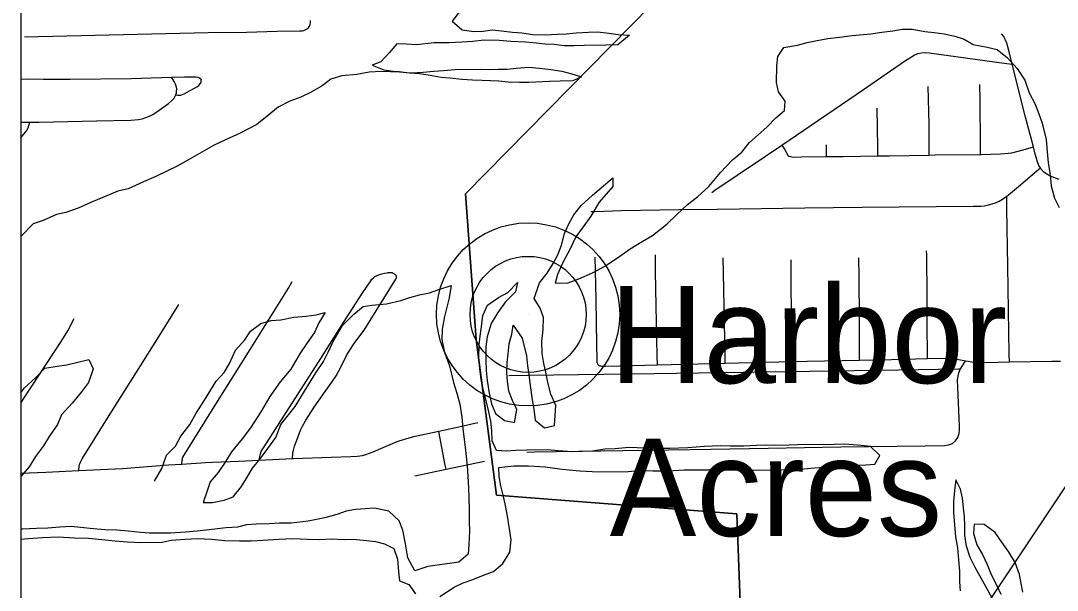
# Model space of a CAD drawing. Extents: x -12 to 34, y 0 to 22.
# Drawn here: x 2.1 to 2.942, y 18.646 to 19.109 of the extents above; entities that cross this region are included whole.
import ezdxf

# ---------------------------------------------------------------- set-up
doc = ezdxf.new("R2010")
doc.units = 0
for name, color, linetype in [('GM_X_Adjacent_County', 7, 'Continuous'), ('GM_X_Airport_Location_Class_2', 7, 'Continuous'), ('GM_X_Interstate_Location', 7, 'Continuous'), ('GM_X_Major_River', 7, 'Continuous'), ('GM_X_Minor_Lake', 7, 'Continuous'), ('GM_X_Section_Text', 7, 'Continuous'), ('GM_X_Township_Subdivision', 7, 'Continuous')]:
    doc.layers.add(name, color=color, linetype=linetype)

msp = doc.modelspace()

# ---------------------------------------------------------------- linework, layer by layer
at = {"layer": 'GM_X_Adjacent_County'}
msp.add_lwpolyline([(4.30775, 20.76949), (2.25839, 17.69538), (4.30775, 20.40004)], close=True, dxfattribs=at)
at = {"layer": 'GM_X_Airport_Location_Class_2'}
for points in [[(2.1, 20.9), (2.1, 15.61304)], [(2.1, 20.9), (2.1, 17.96636)], [(2.68959, 18.49311), (2.68165, 18.70783), (2.48634, 18.72302), (2.46988, 18.8495), (2.4613, 18.96781), (2.96471, 19.47995), (3.12115, 19.56992), (3.19049, 19.59855), (3.18766, 19.70043), (3.36569, 19.80374), (3.38045, 19.82011), (3.38989, 19.8456), (3.42854, 20.1304), (3.40914, 20.1567), (3.40388, 20.16065), (3.39697, 20.15703), (3.38185, 20.15637), (3.37182, 20.18876), (3.3637, 20.21774), (3.34173, 20.25863), (3.3271, 20.27754), (3.2883, 20.32785), (3.27433, 20.35119), (3.21662, 20.37881)], [(3.50022, 20.0768), (3.42854, 20.1304), (3.38989, 19.8456), (3.38045, 19.82011), (3.36569, 19.80374), (3.18766, 19.70043), (3.19049, 19.59855), (3.12115, 19.56992), (2.96471, 19.47995), (2.4613, 18.96781), (2.46988, 18.8495), (2.48634, 18.72302), (2.68165, 18.70783), (2.68959, 18.49311)]]:
    msp.add_lwpolyline(points, dxfattribs=at)
at = {"layer": 'GM_X_Interstate_Location'}
for radius in [0.0744, 0.04716]:
    msp.add_circle((2.51205, 18.86996), radius, dxfattribs=at)
at = {"layer": 'GM_X_Major_River'}
for p, q in [((2.1, 19.0262), (2.10749, 19.02616)), ((2.67207, 18.83038), (2.72649, 18.83162)), ((2.29354, 18.75149), (2.32067, 18.75297)), ((2.44541, 18.74421), (2.47657, 18.75081)), ((2.42013, 18.73885), (2.44541, 18.74421))]:
    msp.add_line(p, q, dxfattribs=at)
for points in [[(2.10297, 19.09531), (2.2523, 19.09884), (2.28331, 19.09936), (2.30812, 19.10009), (2.32677, 19.10024), (2.32848, 19.10033), (2.32988, 19.10062), (2.33104, 19.10102), (2.33258, 19.10181), (2.33308, 19.10219), (2.3337, 19.10278), (2.33448, 19.10405), (2.33502, 19.10541), (2.33536, 19.10696), (2.33542, 19.1087)], [(2.90517, 19.07327), (2.90234, 19.08445), (2.90069, 19.09037), (2.89846, 19.0958), (2.89659, 19.09779)], [(2.71812, 19.00753), (2.78454, 19.05264), (2.81777, 19.07554), (2.82566, 19.08049), (2.82848, 19.08177), (2.83147, 19.08246), (2.83456, 19.08259), (2.83766, 19.08235), (2.89879, 19.07413), (2.90517, 19.07327)], [(2.92239, 19.00597), (2.91606, 19.03019), (2.90517, 19.07327)], [(2.1, 19.06106), (2.10601, 19.06127), (2.11839, 19.06093), (2.14006, 19.06114), (2.1896, 19.06164), (2.22244, 19.06263)], [(2.22244, 19.06263), (2.23294, 19.06293), (2.24221, 19.06283), (2.2437, 19.06266), (2.24475, 19.06228), (2.24554, 19.06188), (2.24617, 19.06128), (2.24652, 19.06039)], [(2.22598, 19.04829), (2.22644, 19.04987), (2.2266, 19.05135), (2.22664, 19.05308), (2.22637, 19.05448), (2.22566, 19.05688), (2.22459, 19.05922), (2.22244, 19.06263)], [(2.22598, 19.04829), (2.22771, 19.04792), (2.23014, 19.04811), (2.23271, 19.04903), (2.24303, 19.0547), (2.24451, 19.05591), (2.24544, 19.05698), (2.24603, 19.05773), (2.24642, 19.05863), (2.24654, 19.05952), (2.24652, 19.06039)], [(2.83769, 18.99937), (2.83769, 19.00576), (2.8377, 19.02425), (2.83703, 19.05507)], [(2.87938, 18.99985), (2.87934, 19.00689), (2.87917, 19.04422), (2.87879, 19.05666)], [(2.10749, 19.02616), (2.11497, 19.02611), (2.16158, 19.02717), (2.18952, 19.02771), (2.19569, 19.02834), (2.19875, 19.02894), (2.20172, 19.02982), (2.20457, 19.031), (2.2073, 19.03244), (2.21248, 19.03589), (2.22005, 19.04137), (2.22254, 19.04336), (2.22454, 19.04564), (2.22598, 19.04829)], [(2.796, 18.99868), (2.79596, 19.00532), (2.79584, 19.02147), (2.79555, 19.03761)], [(2.1, 19.01336), (2.10473, 19.01919), (2.10601, 19.02159), (2.10749, 19.02616)], [(2.66119, 18.96908), (2.66379, 18.97077), (2.68179, 18.98295), (2.70494, 18.99858), (2.71812, 19.00753)], [(2.71812, 19.00753), (2.72014, 19.0042), (2.72337, 18.99887), (2.7239, 18.99852), (2.72755, 18.99779), (2.73371, 18.99801), (2.7544, 18.99818)], [(2.7544, 18.99818), (2.75439, 19.0008), (2.75436, 19.00758)], [(2.796, 18.99868), (2.80536, 18.99882), (2.83769, 18.99937)], [(2.83769, 18.99937), (2.84267, 18.99946), (2.87938, 18.99985)], [(2.87938, 18.99985), (2.88, 18.99986), (2.8956, 19.00028), (2.90184, 19.00081), (2.90495, 19.00133), (2.91403, 19.00374), (2.92239, 19.00597)], [(2.92808, 18.98902), (2.92685, 18.99103), (2.9256, 18.99399), (2.92392, 19.00012), (2.92239, 19.00597)], [(2.7544, 18.99818), (2.76801, 18.99828), (2.796, 18.99868)], [(2.9007, 18.96608), (2.90226, 18.96721), (2.9118, 18.97516), (2.92362, 18.98523), (2.92808, 18.98902)], [(2.94326, 18.97953), (2.93907, 18.98109), (2.93614, 18.98234), (2.93332, 18.98388), (2.93073, 18.98581), (2.92855, 18.98825), (2.92808, 18.98902)], [(2.56304, 18.95352), (2.56614, 18.95368), (2.58787, 18.95443), (2.63444, 18.95508), (2.66548, 18.95554), (2.7369, 18.95651), (2.78347, 18.95698), (2.87351, 18.95777), (2.87972, 18.95794), (2.8828, 18.95827), (2.88584, 18.95886), (2.88884, 18.95967), (2.89175, 18.96072), (2.89457, 18.96202), (2.89725, 18.96356), (2.9007, 18.96608)], [(2.90289, 18.83132), (2.90279, 18.83767), (2.90164, 18.90919), (2.90087, 18.95583), (2.9007, 18.96608)], [(2.56889, 18.82902), (2.56832, 18.83009), (2.56814, 18.83087), (2.56811, 18.8337), (2.56779, 18.84516), (2.56737, 18.88231), (2.56647, 18.91636)], [(2.61711, 18.82901), (2.61695, 18.8363), (2.61611, 18.87681), (2.61552, 18.90486), (2.61538, 18.91832)], [(2.67207, 18.83038), (2.67199, 18.83522), (2.67156, 18.86313), (2.67068, 18.90342), (2.6704, 18.91582)], [(2.78124, 18.83272), (2.78121, 18.83782), (2.78105, 18.86589), (2.78088, 18.9002), (2.78066, 18.9158)], [(2.83641, 18.83421), (2.83634, 18.83984), (2.83611, 18.85871), (2.8361, 18.8933), (2.83589, 18.90901), (2.83578, 18.91844), (2.83569, 18.92157)], [(2.72649, 18.83162), (2.7264, 18.8386), (2.72569, 18.89218), (2.72556, 18.91424)], [(2.29354, 18.75149), (2.29386, 18.75354), (2.29463, 18.75661), (2.29539, 18.75857), (2.34363, 18.83426), (2.36209, 18.86325), (2.37718, 18.88707), (2.38424, 18.89731), (2.38525, 18.89845), (2.38637, 18.89956), (2.38769, 18.90063), (2.38936, 18.90163), (2.39125, 18.90239), (2.39322, 18.90293), (2.39545, 18.90335), (2.39787, 18.90367)], [(2.32067, 18.75297), (2.32109, 18.7573), (2.32158, 18.75981), (2.32242, 18.76281), (2.32501, 18.77), (2.3272, 18.77584), (2.32848, 18.77866), (2.3315, 18.78408), (2.33824, 18.79456), (2.34725, 18.80727), (2.35275, 18.81483), (2.35611, 18.82005), (2.36061, 18.82821), (2.36466, 18.83663), (2.36616, 18.83935), (2.37139, 18.84706), (2.37884, 18.85704), (2.40454, 18.89855), (2.40507, 18.89959), (2.40524, 18.90021), (2.4052, 18.90091), (2.4049, 18.90152), (2.40395, 18.9023), (2.40312, 18.90289), (2.40255, 18.90321), (2.40165, 18.90364), (2.40054, 18.90384), (2.39787, 18.90367)], [(2.2309, 18.74839), (2.23109, 18.7517), (2.23126, 18.75269), (2.2317, 18.754), (2.2584, 18.79715), (2.28639, 18.84152), (2.30926, 18.87818), (2.31741, 18.89127), (2.32045, 18.89664)], [(2.14731, 18.74311), (2.14736, 18.74657), (2.14761, 18.748), (2.14846, 18.75002), (2.14976, 18.75272), (2.17051, 18.78561), (2.19727, 18.82827), (2.21368, 18.85435), (2.22828, 18.87795)], [(2.1, 18.79791), (2.10287, 18.80213), (2.13342, 18.84872), (2.13819, 18.85668), (2.14331, 18.8666)], [(2.72649, 18.83162), (2.73879, 18.8319), (2.78124, 18.83272)], [(2.78124, 18.83272), (2.80717, 18.83323), (2.83641, 18.83421)], [(2.83641, 18.83421), (2.84138, 18.83438), (2.85388, 18.83427), (2.85701, 18.83409), (2.86324, 18.83312), (2.86733, 18.83231)], [(2.86333, 18.82583), (2.86557, 18.82946), (2.86733, 18.83231)], [(2.86733, 18.83231), (2.8693, 18.83191), (2.87232, 18.8314), (2.88461, 18.83097), (2.90289, 18.83132)], [(2.90289, 18.83132), (2.93744, 18.83198), (2.94454, 18.83208)], [(2.4965, 18.8203), (2.512, 18.82059), (2.61437, 18.82197), (2.81289, 18.82504), (2.86156, 18.8258), (2.86333, 18.82583)], [(2.5111, 18.75817), (2.51731, 18.75839), (2.58884, 18.75953), (2.62615, 18.75994), (2.66039, 18.76051), (2.70703, 18.76133), (2.76614, 18.76233), (2.83456, 18.76329), (2.85019, 18.76358), (2.85342, 18.76402), (2.85657, 18.76513), (2.85927, 18.76718), (2.86113, 18.77), (2.86209, 18.77313), (2.86242, 18.77636), (2.86241, 18.77956), (2.86096, 18.81071), (2.86088, 18.81687), (2.86118, 18.81984), (2.86193, 18.82263), (2.86291, 18.82514), (2.86333, 18.82583)], [(2.56889, 18.82902), (2.56957, 18.82848), (2.57029, 18.82822), (2.57107, 18.82808), (2.57203, 18.82804), (2.57465, 18.82803), (2.58646, 18.82815), (2.61711, 18.82901)], [(2.61711, 18.82901), (2.6393, 18.82963), (2.67207, 18.83038)], [(2.4395, 18.77517), (2.45325, 18.7782), (2.4712, 18.78226)], [(2.39446, 18.76181), (2.40574, 18.76664), (2.41155, 18.76862), (2.42043, 18.77095), (2.4395, 18.77517)], [(2.44541, 18.74421), (2.44476, 18.7476), (2.44037, 18.77062), (2.4395, 18.77517)], [(2.32067, 18.75297), (2.32144, 18.75301), (2.35216, 18.75391), (2.36816, 18.75442), (2.37329, 18.7548), (2.37764, 18.75545), (2.3803, 18.75614), (2.38613, 18.75829), (2.39446, 18.76181)], [(2.14731, 18.74311), (2.18276, 18.74482), (2.2201, 18.74763), (2.2309, 18.74839)], [(2.2309, 18.74839), (2.25012, 18.74974), (2.25566, 18.74999)], [(2.25566, 18.74999), (2.277, 18.7507), (2.29354, 18.75149)], [(2.1, 18.74098), (2.12045, 18.74182), (2.14731, 18.74311)]]:
    msp.add_lwpolyline(points, dxfattribs=at)
at = {"layer": 'GM_X_Minor_Lake'}
for points in [[(2.45685, 19.11657), (2.45044, 19.10818), (2.45845, 19.10099), (2.46795, 19.09989), (2.47554, 19.09993), (2.48275, 19.1011), (2.49035, 19.10038), (2.49946, 19.09928), (2.50706, 19.09856), (2.5158, 19.09746), (2.52605, 19.09713), (2.53592, 19.09755), (2.54313, 19.09797), (2.5511, 19.09877), (2.56097, 19.09919), (2.56856, 19.09961), (2.57768, 19.09851), (2.58528, 19.09741), (2.59439, 19.09669), (2.58494, 19.08904), (2.57507, 19.08861), (2.55761, 19.08853), (2.54926, 19.08811), (2.54129, 19.08807), (2.53293, 19.08918), (2.52571, 19.08952), (2.51849, 19.09025), (2.51014, 19.09097), (2.49799, 19.09167), (2.48849, 19.09239), (2.47634, 19.09271), (2.46685, 19.09152), (2.45812, 19.0911), (2.44787, 19.09067), (2.43573, 19.09061), (2.42131, 19.08903), (2.41295, 19.08936), (2.40536, 19.08971), (2.39932, 19.08246), (2.39252, 19.0752), (2.38532, 19.0725), (2.39484, 19.06875), (2.40434, 19.06727), (2.41687, 19.06619), (2.42674, 19.06662), (2.43547, 19.06742), (2.44344, 19.06822), (2.45292, 19.06902), (2.47342, 19.06912), (2.48064, 19.06877), (2.48785, 19.06919), (2.49506, 19.06922), (2.50227, 19.07002), (2.51252, 19.07083), (2.52126, 19.07011), (2.53037, 19.06901), (2.53949, 19.06753), (2.54748, 19.06529)], [(2.49588, 18.83804), (2.4966, 18.84603), (2.49883, 18.85403), (2.49994, 18.86126), (2.5072, 18.85065), (2.5107, 18.83621), (2.51149, 18.82823), (2.51267, 18.82101), (2.51385, 18.81227), (2.51544, 18.80049), (2.51661, 18.7929), (2.5178, 18.78416), (2.52542, 18.77773), (2.53339, 18.77967), (2.53444, 18.79602), (2.5306, 18.80513), (2.52828, 18.81348), (2.52633, 18.82298), (2.52477, 18.8302), (2.52359, 18.83818), (2.52316, 18.84806), (2.52425, 18.85757), (2.52458, 18.86746), (2.52188, 18.87505), (2.51691, 18.88301), (2.5214, 18.89558), (2.52743, 18.90359), (2.53233, 18.91122), (2.53609, 18.91846), (2.53909, 18.92608), (2.54169, 18.9356), (2.54507, 18.9436), (2.54921, 18.95084), (2.55524, 18.95848), (2.56431, 18.96689), (2.57338, 18.97453), (2.58095, 18.98103), (2.58098, 18.97381), (2.56966, 18.96121), (2.56288, 18.94977), (2.55685, 18.94099), (2.55082, 18.93298), (2.54594, 18.92269), (2.5403, 18.91202), (2.53579, 18.90249), (2.53393, 18.89526), (2.54456, 18.89569), (2.55327, 18.89877), (2.56426, 18.90377), (2.57486, 18.90952), (2.58659, 18.91718), (2.59491, 18.9233), (2.60475, 18.92905), (2.61308, 18.93404), (2.6248, 18.94322), (2.63273, 18.95124), (2.64142, 18.95927), (2.64974, 18.96539), (2.65881, 18.9738), (2.66824, 18.98525), (2.67806, 18.99556), (2.68562, 19.00168), (2.69166, 19.00932), (2.69884, 19.01581), (2.70602, 19.02193), (2.7132, 19.02957), (2.72038, 19.03569), (2.72072, 19.0433), (2.71536, 19.05087), (2.71381, 19.05847), (2.71412, 19.07178), (2.71484, 19.07939), (2.71974, 19.08664), (2.73073, 19.08859), (2.7387, 19.09091), (2.74666, 19.09247), (2.75539, 19.09403), (2.76487, 19.09522), (2.77512, 19.09641), (2.79029, 19.098), (2.7994, 19.09918), (2.80813, 19.10037), (2.81571, 19.10154), (2.82407, 19.10158), (2.83433, 19.09973), (2.84192, 19.09901), (2.8499, 19.0979), (2.85864, 19.09604), (2.86625, 19.09342), (2.87348, 19.08927), (2.88489, 19.08704), (2.89287, 19.08518), (2.90126, 19.07837), (2.90927, 19.06967), (2.9154, 19.06019), (2.91887, 19.04994), (2.92347, 19.04122), (2.92693, 19.03287), (2.92963, 19.02527), (2.93273, 19.01198), (2.93354, 19.0021)], [(2.54748, 19.06529), (2.55546, 19.06304), (2.54827, 19.05959), (2.53802, 19.05954), (2.52929, 19.05912), (2.51259, 19.05828), (2.50499, 19.05824), (2.49588, 19.05858), (2.48828, 19.0593), (2.47461, 19.06), (2.46702, 19.06034), (2.45828, 19.06068), (2.44878, 19.06178), (2.44157, 19.0625), (2.43245, 19.06398), (2.42371, 19.06546), (2.41573, 19.0658), (2.40737, 19.0669), (2.40016, 19.06687), (2.39295, 19.06722), (2.38308, 19.06679), (2.37284, 19.06484), (2.36069, 19.06364), (2.35197, 19.06094), (2.34479, 19.05558), (2.33532, 19.05021), (2.32737, 19.04637), (2.31866, 19.04329), (2.30919, 19.0383), (2.30011, 19.03103), (2.2918, 19.02415), (2.27817, 19.01724), (2.26642, 19.01186), (2.25658, 19.00725), (2.24711, 19.00188), (2.23576, 18.99536), (2.22705, 18.99038), (2.2191, 18.98654), (2.20963, 18.98193), (2.19978, 18.9777), (2.18728, 18.97194), (2.17894, 18.97), (2.16681, 18.965), (2.15734, 18.96115), (2.14674, 18.95616), (2.13651, 18.95268), (2.12892, 18.95113), (2.11832, 18.94614), (2.10998, 18.94343), (2.1, 18.93334)], [(2.93354, 19.0021), (2.93435, 18.99298), (2.93592, 18.98348), (2.93672, 18.97436), (2.93943, 18.96448), (2.94327, 18.9569)], [(2.20863, 18.7344), (2.21465, 18.7447), (2.21839, 18.75574), (2.22557, 18.763), (2.23008, 18.771), (2.23724, 18.78054), (2.24251, 18.78969), (2.24929, 18.80037), (2.25871, 18.81562), (2.26512, 18.82288), (2.26964, 18.83012), (2.27452, 18.84079), (2.28207, 18.84919), (2.28659, 18.85644), (2.29491, 18.86256), (2.30325, 18.86488), (2.31122, 18.86568), (2.32184, 18.86763), (2.33171, 18.86844), (2.34005, 18.86962), (2.34726, 18.87156), (2.34199, 18.86317), (2.33861, 18.85517), (2.33258, 18.84677), (2.32693, 18.83838), (2.3194, 18.82542), (2.31072, 18.81511), (2.30243, 18.80329), (2.2949, 18.7907), (2.28662, 18.77773), (2.27983, 18.76896), (2.27115, 18.75827), (2.26663, 18.75065), (2.26023, 18.74149), (2.25381, 18.73386), (2.25082, 18.7251), (2.2482, 18.7171), (2.2558, 18.71714), (2.26528, 18.71908), (2.27248, 18.72178), (2.27927, 18.73018), (2.28378, 18.7378), (2.2883, 18.74505), (2.29434, 18.75268), (2.30075, 18.76107), (2.30716, 18.76985), (2.31128, 18.78051), (2.32297, 18.79502), (2.3305, 18.8076), (2.33954, 18.82247), (2.34595, 18.83163), (2.3497, 18.83925), (2.35383, 18.84801), (2.36136, 18.86098), (2.37042, 18.87015), (2.37798, 18.87626), (2.3852, 18.87744), (2.39696, 18.87864), (2.40871, 18.88135), (2.41591, 18.88367), (2.42388, 18.88599), (2.43184, 18.88755), (2.43942, 18.89025), (2.44965, 18.89334), (2.44781, 18.88344), (2.44409, 18.86822), (2.44224, 18.85794), (2.44191, 18.84957), (2.44424, 18.83894), (2.44809, 18.82831), (2.45158, 18.81464), (2.45428, 18.80591), (2.4566, 18.79717), (2.45818, 18.78654), (2.45899, 18.77703), (2.46096, 18.76221), (2.46256, 18.74701), (2.46338, 18.73409), (2.46382, 18.72231), (2.46427, 18.71014), (2.46431, 18.70178), (2.46435, 18.69379), (2.46402, 18.68315), (2.46331, 18.67516), (2.45575, 18.66866), (2.44816, 18.66748), (2.4383, 18.6663), (2.43071, 18.66512), (2.4201, 18.66165), (2.41435, 18.67227), (2.41239, 18.68366), (2.41043, 18.69468), (2.40736, 18.70227), (2.39896, 18.71021), (2.38718, 18.71244), (2.37997, 18.71202), (2.372, 18.71161), (2.36442, 18.71005), (2.35684, 18.70735), (2.34698, 18.70464), (2.33332, 18.70192)], [(2.48388, 18.66119), (2.49144, 18.66769), (2.49709, 18.67684), (2.49818, 18.68673), (2.49699, 18.69585), (2.49503, 18.70763), (2.49347, 18.71598), (2.49191, 18.7232), (2.48998, 18.73079), (2.48842, 18.73839), (2.48838, 18.74562), (2.50052, 18.74682), (2.51229, 18.74687), (2.52597, 18.74617), (2.53964, 18.74434), (2.55408, 18.74289), (2.56927, 18.7422), (2.59319, 18.74231), (2.60153, 18.74311), (2.6133, 18.74279), (2.62545, 18.74284), (2.63874, 18.74367), (2.66076, 18.74377), (2.67177, 18.74345), (2.71391, 18.74365), (2.7215, 18.74406), (2.73023, 18.7441), (2.74466, 18.74531), (2.7568, 18.74613), (2.76553, 18.74655), (2.77502, 18.74736), (2.78641, 18.74779), (2.79362, 18.74821), (2.79776, 18.75545), (2.79012, 18.76264), (2.77987, 18.76373), (2.76885, 18.76444), (2.7605, 18.7644), (2.75063, 18.76397), (2.73696, 18.76429), (2.72406, 18.76384), (2.71191, 18.76341), (2.7047, 18.76375), (2.69748, 18.76334), (2.68723, 18.76291), (2.67623, 18.76286), (2.66825, 18.7632), (2.65534, 18.76276), (2.64168, 18.76155), (2.62688, 18.7611), (2.61435, 18.76104), (2.59385, 18.76171), (2.58284, 18.76089), (2.57449, 18.76047), (2.56425, 18.7589), (2.55589, 18.75848), (2.54792, 18.75845), (2.53653, 18.75915), (2.52817, 18.75987), (2.51109, 18.75979), (2.50198, 18.75937), (2.49439, 18.75895), (2.48641, 18.75929), (2.48296, 18.76726), (2.48254, 18.77525), (2.48173, 18.78322), (2.48018, 18.79082), (2.47824, 18.7988), (2.47553, 18.80905), (2.47397, 18.81703), (2.47278, 18.82615), (2.47198, 18.83451), (2.4723, 18.84515), (2.47302, 18.85238), (2.47412, 18.85999), (2.47522, 18.86912), (2.47897, 18.87751), (2.48805, 18.88363), (2.49562, 18.88785), (2.50355, 18.89587), (2.5017, 18.88826), (2.49376, 18.88024), (2.48735, 18.87146), (2.48208, 18.86269), (2.47872, 18.85165), (2.47762, 18.84366), (2.47768, 18.83301), (2.4781, 18.82427), (2.47891, 18.81629), (2.48048, 18.80603), (2.48242, 18.7973), (2.4855, 18.78933), (2.49274, 18.78366), (2.5011, 18.78218), (2.50295, 18.79283), (2.49949, 18.80004), (2.49641, 18.80763), (2.49523, 18.81561), (2.49482, 18.82283), (2.49516, 18.83082), (2.49588, 18.83804)], [(2.1, 18.80635), (2.10269, 18.80994), (2.11214, 18.81873), (2.11969, 18.82637), (2.12956, 18.82794), (2.13752, 18.82911), (2.14625, 18.83106), (2.15534, 18.83338), (2.1588, 18.82579), (2.15506, 18.81475), (2.14941, 18.80712), (2.14186, 18.79796), (2.13318, 18.78841), (2.1298, 18.78041), (2.12302, 18.77088), (2.1185, 18.76325), (2.11209, 18.75447), (2.10682, 18.74608), (2.1, 18.73829)], [(2.88909, 18.63878), (2.88411, 18.64826), (2.87491, 18.66495), (2.87108, 18.67254), (2.86799, 18.68164), (2.86681, 18.69038), (2.86677, 18.69837), (2.86635, 18.70559), (2.86555, 18.71281), (2.86475, 18.72079), (2.8632, 18.72801), (2.85936, 18.73559), (2.85827, 18.72684), (2.85755, 18.71809)], [(2.85755, 18.71809), (2.8576, 18.70897), (2.85841, 18.69909), (2.85922, 18.68921), (2.86078, 18.68047), (2.86159, 18.67059), (2.8624, 18.66147), (2.86245, 18.65272), (2.86286, 18.6455)], [(2.33332, 18.70192), (2.31966, 18.70033), (2.31017, 18.70029), (2.30182, 18.69987), (2.2912, 18.69944), (2.28322, 18.69902), (2.27602, 18.69708), (2.26691, 18.69666), (2.2506, 18.69468), (2.24339, 18.69389), (2.2339, 18.69308), (2.22175, 18.69226), (2.20467, 18.69218), (2.19745, 18.69291), (2.1872, 18.694), (2.17808, 18.69472), (2.16821, 18.69505), (2.15909, 18.69577), (2.14846, 18.69686), (2.14086, 18.69758), (2.13175, 18.69716), (2.12188, 18.69635), (2.11277, 18.69593), (2.10138, 18.69549), (2.1, 18.69541)], [(2.91374, 18.64422), (2.91257, 18.65144), (2.91101, 18.65866), (2.90754, 18.66853), (2.90218, 18.67724), (2.89683, 18.68482), (2.89147, 18.69278), (2.88233, 18.6992), (2.87435, 18.69954), (2.87363, 18.69193), (2.87634, 18.68283), (2.88093, 18.67486), (2.88477, 18.6669), (2.88823, 18.65855), (2.89207, 18.65096), (2.89591, 18.64262)], [(2.1, 18.68748), (2.10598, 18.68791), (2.11774, 18.68873), (2.13027, 18.68917), (2.14356, 18.68847), (2.15495, 18.68814), (2.16597, 18.68705), (2.17661, 18.68597), (2.18648, 18.68525), (2.19749, 18.68454), (2.21496, 18.68501), (2.22216, 18.68656), (2.23355, 18.68738), (2.24342, 18.6878), (2.25519, 18.68748), (2.26582, 18.68639), (2.27759, 18.68606), (2.28709, 18.68611), (2.29658, 18.68653), (2.30948, 18.68736), (2.32087, 18.68779), (2.33302, 18.68747), (2.34251, 18.68713), (2.352, 18.68756), (2.36263, 18.68723), (2.36985, 18.68726), (2.38086, 18.68617), (2.38808, 18.68545), (2.3953, 18.68358), (2.40292, 18.67982), (2.406, 18.67108), (2.40681, 18.66083), (2.40761, 18.65361), (2.41522, 18.6506), (2.42057, 18.64302)], [(2.44032, 18.64083), (2.45205, 18.64849), (2.45925, 18.65195), (2.46721, 18.65465), (2.47592, 18.65811), (2.48388, 18.66119)]]:
    msp.add_lwpolyline(points, dxfattribs=at)
at = {"layer": 'GM_X_Township_Subdivision'}
msp.add_line((2.51205, 18.86996), (2.51205, 18.86996), dxfattribs=at)

# ---------------------------------------------------------------- texts
at = {"layer": 'GM_X_Section_Text'}
for s, p in [('Harbor', (2.57826, 18.81411)), ('Acres', (2.57826, 18.68994))]:
    msp.add_text(s, height=0.078977, rotation=0.00001, dxfattribs=at).set_placement(p)

doc.saveas('drawing.dxf')
